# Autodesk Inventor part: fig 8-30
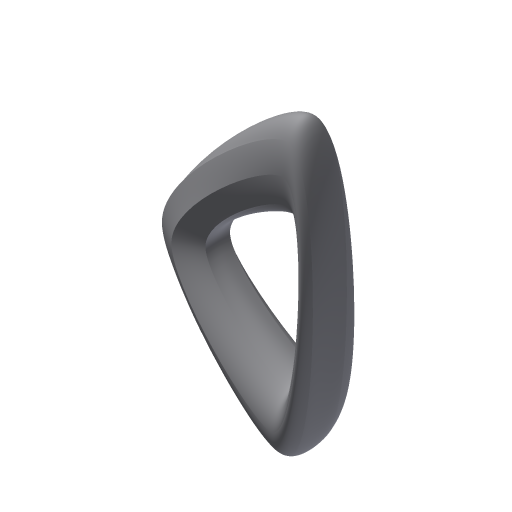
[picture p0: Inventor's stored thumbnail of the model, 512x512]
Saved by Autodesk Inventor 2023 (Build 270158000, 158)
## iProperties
Created: 2008-06
Part Number: fig 8-30
Document SubType Name: Modeling
Designer: CADCIM
Density: 1 g/cm^3
Material: Generic
Appearance: Default
Author: CADCIM
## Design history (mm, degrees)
sketch "Sketch1"
  geometry: L1 (-0.077, 5.773)-(4.961, 2.953); L2 (4.961, 2.953)-(5.038, -2.82); L3 (5.038, -2.82)-(0.077, -5.773); L4 (0.077, -5.773)-(-4.961, -2.953); L5 (-4.961, -2.953)-(-5.038, 2.82); L6 (-5.038, 2.82)-(-0.077, 5.773); 1 further point
  constraints: 12 end point, 13 other
  dimensions: "d0" = 10 distance between parallel lines of L2 L5
workplane "Work Plane1"
sketch "Sketch2"
  geometry: C1 r 7.5 at (-0.159, -25); 1 further point
  constraints: 1 centre point
  dimensions: "d2" = 15 diameter of C1; "d3" = 25 vertical distance of C1.centre point (0, 0)
sketch "Sketch3" dims "d4" = 10, "d5" = 5
  geometry: 2 further points; 1 other entity
  constraints: 2 other
  dimensions: "d6" = 25 vertical distance of point (0.175, 25) point (0, 0)
loft "Loft1" sketch "Sketch2", "Sketch3" dims "d7" = 0, "d8" = 90 deg, "d9" = 0, "d10" = 90 deg, "d11" = 0, "d12" = 90 deg
body "Solid1"
other parameters: "d1" = 25
